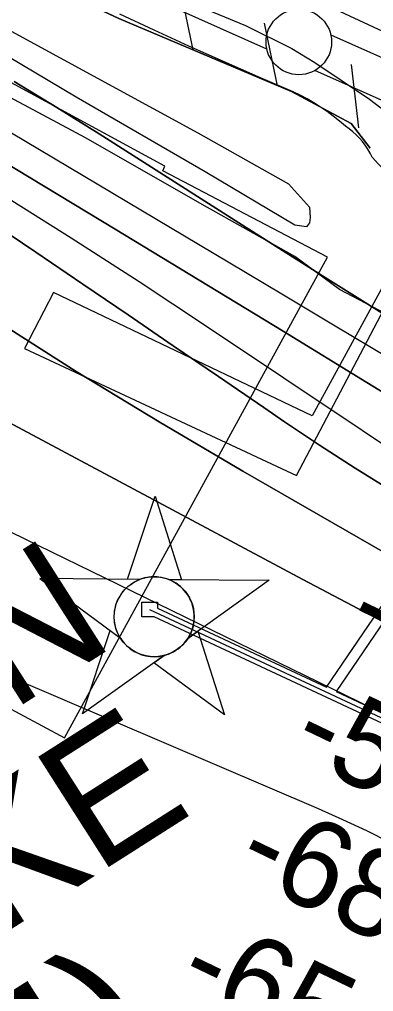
# Model space of a CAD drawing. Extents: x 3704301 to 3742427, y 506229 to 532009.
# Drawn here: x 3708909 to 3709180, y 522807 to 523550 of the extents above; entities that cross this region are included whole.
import ezdxf

# ---------------------------------------------------------------- set-up
doc = ezdxf.new("R2010")
doc.units = 0
for name, color, linetype in [('V-CHAN-DOCK', 7, 'Continuous'), ('V-CHAN-NAID', 7, 'Continuous'), ('V-FLOD-BASE', 7, 'Continuous'), ('V-LEVE-TOET', 7, 'Continuous'), ('V-RIVR-EDGE', 7, 'Continuous'), ('V-RIVR-RANG', 7, 'Continuous'), ('V-RRAP-FSHR', 7, 'Continuous'), ('V-RRAP-RVMT', 7, 'Continuous'), ('V-SITE-VEGE', 7, 'Continuous'), ('V-SURV-LINE', 7, 'Continuous'), ('V-TOPO-DPTH', 7, 'Continuous'), ('V-TOPO-MAJR', 7, 'Continuous'), ('V-TOPO-MINR', 7, 'Continuous'), ('V-TOPO-WATR', 7, 'Continuous'), ('V-UTIL-LINE', 7, 'Continuous')]:
    doc.layers.add(name, color=color, linetype=linetype)

msp = doc.modelspace()

# ---------------------------------------------------------------- linework, layer by layer
at = {"layer": 'V-CHAN-DOCK'}
for points in [[(3709201.26, 523372.33), (3709132.68, 523246.8), (3708935.23, 523340.97), (3708913.04, 523298.3), (3709120.9, 523201.18), (3709208.21, 523367.89), (3709201.26, 523372.33)], [(3709143.74, 523039.46), (3709223.58, 523156.83), (3709280.37, 523238.73), (3709347.55, 523327.59), (3709353.71, 523322.56), (3709286.53, 523233.7), (3709229.73, 523151.8), (3709151, 523036.06), (3709270.29, 522980.22), (3709280.08, 522980.2), (3709280.05, 522969.09), (3709268.05, 522969.11), (3709268.06, 522973.54), (3709012.15, 523093.33), (3709002.64, 523093.35), (3709002.67, 523104.47), (3709014.67, 523104.44), (3709014.66, 523099.89), (3709143.74, 523039.46)]]:
    msp.add_lwpolyline(points, dxfattribs=at)
at = {"layer": 'V-CHAN-NAID'}
for points in [[(3709001.26, 523121.87), (3708991.67, 523121.94), (3709012.8, 523185.42), (3709033.02, 523121.64), (3709023.43, 523121.71), (3709021.86, 523122.29), (3709019.76, 523122.91), (3709017.72, 523123.36), (3709015.69, 523123.67), (3709014.52, 523123.78), (3709012.98, 523123.86), (3709011.26, 523123.86), (3709009.89, 523123.79), (3709007.99, 523123.59), (3709006.62, 523123.37), (3709004.84, 523122.99), (3709003.31, 523122.57), (3709002.27, 523122.24)], [(3709001.26, 523121.87), (3708924.77, 523122.41), (3708986.33, 523077.01), (3708985.22, 523078.92), (3708984.41, 523080.55), (3708983.58, 523082.52), (3708982.89, 523084.57), (3708982.52, 523085.89), (3708982.16, 523087.52), (3708981.92, 523088.96), (3708981.73, 523090.56), (3708981.62, 523092.3), (3708981.61, 523093.88), (3708981.72, 523095.95), (3708981.9, 523097.57), (3708982.29, 523099.77), (3708982.77, 523101.7), (3708983.38, 523103.58), (3708984.03, 523105.26), (3708984.76, 523106.85), (3708985.57, 523108.39), (3708986.63, 523110.12), (3708987.66, 523111.59), (3708988.66, 523112.86), (3708989.67, 523114.01), (3708990.97, 523115.35), (3708992.02, 523116.31), (3708993.74, 523117.71), (3708994.95, 523118.58), (3708996.64, 523119.65), (3708998.37, 523120.59), (3708999.82, 523121.28)], [(3709023.43, 523121.71), (3709099.93, 523121.17), (3709037.72, 523076.65), (3709038.63, 523078.14), (3709039.61, 523079.98), (3709040.33, 523081.57), (3709041.07, 523083.52), (3709041.61, 523085.31), (3709042.01, 523086.95), (3709042.37, 523088.96), (3709042.56, 523090.53), (3709042.68, 523092.73), (3709042.65, 523094.8), (3709042.46, 523097.02), (3709042.2, 523098.78), (3709041.71, 523101.01), (3709041.06, 523103.15), (3709040.31, 523105.13), (3709039.67, 523106.57), (3709038.66, 523108.49), (3709037.6, 523110.21), (3709036.38, 523111.91), (3709035.12, 523113.45), (3709033.85, 523114.82), (3709032.22, 523116.35), (3709030.48, 523117.76), (3709028.79, 523118.94), (3709026.91, 523120.07), (3709025.43, 523120.83)], [(3709019.69, 523063.74), (3708957.49, 523019.22), (3708978.62, 523082.7), (3708986.33, 523077.01), (3708986.97, 523076.05), (3708988.35, 523074.19), (3708989.56, 523072.77), (3708991.03, 523071.27), (3708992.42, 523070.02), (3708993.87, 523068.86), (3708995.27, 523067.88), (3708996.95, 523066.84), (3708998.67, 523065.93), (3709000.46, 523065.12), (3709001.9, 523064.56), (3709003.53, 523064.03), (3709005.76, 523063.47), (3709007.29, 523063.18), (3709009.31, 523062.92), (3709010.85, 523062.82), (3709012.71, 523062.8), (3709014.4, 523062.88), (3709016.11, 523063.05), (3709018.01, 523063.36)], [(3709037.72, 523076.65), (3709045.52, 523082.23), (3709065.74, 523018.45), (3709011.9, 523058.16), (3709019.69, 523063.74), (3709021.36, 523064.22), (3709022.97, 523064.78), (3709025.13, 523065.69), (3709026.86, 523066.57), (3709028.73, 523067.69), (3709030.47, 523068.9), (3709032.02, 523070.15), (3709033.31, 523071.31), (3709034.69, 523072.73), (3709035.9, 523074.14), (3709037.01, 523075.61)]]:
    msp.add_lwpolyline(points, close=True, dxfattribs=at)
msp.add_circle((3709012.14, 523093.33), 30.54, dxfattribs=at)
at = {"layer": 'V-FLOD-BASE'}
msp.add_lwpolyline([(3708672.81, 523755.58), (3708745.33, 523708.9), (3708803.64, 523671.65), (3708829.23, 523656.1), (3708842.97, 523649.03), (3708909.77, 523618.9), (3708991.73, 523582.65), (3709081.74, 523545.01), (3709117.28, 523527.58), (3709134.82, 523516.74), (3709176.53, 523488.92), (3709185.06, 523482.31), (3709195.03, 523472.87), (3709199.78, 523465.31), (3709202.16, 523459.63), (3709201.23, 523449.22), (3709198.42, 523437.86)], dxfattribs=at)
at = {"layer": 'V-LEVE-TOET'}
for points in [[(3709197.72, 523535.35), (3709110.54, 523576.31), (3709007.73, 523622.45), (3708906.81, 523670.48), (3708855.63, 523696.86), (3708767.94, 523754.86), (3708757.73, 523761.46)], [(3709178.5, 523444.5), (3709176.93, 523447.62), (3709175.17, 523450.65), (3709173.22, 523453.56), (3709171.09, 523456.36), (3709168.79, 523459.02), (3709166.33, 523461.54), (3709163.72, 523463.9), (3709160.97, 523466.09), (3709158.09, 523468.12), (3709153.56, 523472.04), (3709148.89, 523475.79), (3709144.08, 523479.37), (3709139.15, 523482.77), (3709134.09, 523485.99), (3709128.93, 523489.03), (3709123.65, 523491.87), (3709118.28, 523494.52), (3709091.61, 523505.96), (3709065.02, 523517.6), (3709038.52, 523529.42), (3709012.11, 523541.45), (3708985.79, 523553.67)], [(3709178.5, 523444.5), (3709183.37, 523439.05), (3709203.89, 523419.31), (3709245.21, 523401.81), (3709256.13, 523405.48), (3709284.61, 523404.06)]]:
    msp.add_lwpolyline(points, dxfattribs=at)
at = {"layer": 'V-RIVR-EDGE'}
msp.add_lwpolyline([(3709189.1, 523324.66), (3709153.73, 523343.35), (3709119.57, 523368.65), (3709048.83, 523408.45), (3708960.11, 523459.1), (3708883.37, 523500.11)], dxfattribs=at)
at = {"layer": 'V-RRAP-FSHR'}
for p, q in [((3709041.95, 523526.47), (3709031.79, 523574.23)), ((3709106.39, 523499.13), (3709096.23, 523546.89)), ((3709168.49, 523466.91), (3709162.78, 523515.4))]:
    msp.add_line(p, q, dxfattribs=at)
for points in [[(3709177.03, 523451.36), (3709162.4, 523470.19), (3709116.88, 523494.68), (3708985.22, 523550.53), (3708890.26, 523595.17), (3708817.73, 523631.58), (3708708.88, 523704.05), (3708608.24, 523768.9), (3708492.61, 523832.14)], [(3708917.78, 523582.24), (3708985.22, 523550.53), (3709116.88, 523494.68), (3709162.4, 523470.19), (3709177.03, 523451.36)], [(3708933.6, 523574.8), (3708985.22, 523550.53), (3709116.88, 523494.68), (3709162.4, 523470.19), (3709177.03, 523451.36)]]:
    msp.add_lwpolyline(points, dxfattribs=at)
at = {"layer": 'V-RRAP-RVMT'}
for p, q in [((3709020.35, 523437.59), (3708894.02, 523506.06)), ((3709018.83, 523434.1), (3709020.35, 523437.59)), ((3709144.49, 523368.14), (3709018.83, 523434.1)), ((3708943.58, 523000.86), (3709144.49, 523368.14)), ((3708432.94, 523273.93), (3708943.58, 523000.86))]:
    msp.add_line(p, q, dxfattribs=at)
at = {"layer": 'V-SITE-VEGE'}
msp.add_lwpolyline([(3708874.63, 523556.08), (3709045.52, 523463.12), (3709114.6, 523424.04), (3709130.69, 523406.24), (3709131.31, 523398.51), (3709130.72, 523394.34), (3709128.35, 523391.36), (3709119.43, 523392.53), (3709050.95, 523433.4), (3708952.69, 523490.25), (3708878.85, 523534.08)], dxfattribs=at)
at = {"layer": 'V-SURV-LINE'}
for points in [[(3709098.2, 523526.99), (3708942.29, 523596.92)], [(3709146.91, 523538.08), (3709674.37, 523303.1)], [(3709662.17, 523275.69), (3709134.71, 523510.67)]]:
    msp.add_lwpolyline(points, dxfattribs=at)
msp.add_circle((3709122.56, 523532.5), 25, dxfattribs=at)
at = {"layer": 'V-TOPO-DPTH'}
for points in [[(3708905.29, 523502.3), (3708937.88, 523482.44), (3708970.25, 523462.21), (3709079.62, 523392.57), (3709110.14, 523373.2), (3709140.69, 523353.87), (3709171.28, 523334.63), (3709201.92, 523315.44)], [(3708812.76, 523491.81), (3708918.01, 523428.33), (3708982.24, 523389.49), (3709046.42, 523350.55), (3709110.51, 523311.48), (3709174.54, 523272.31), (3709245.62, 523228.72), (3709274.39, 523211.89), (3709303.58, 523195.88), (3709333.42, 523181.1), (3709363.68, 523167.13), (3709377.41, 523161.13), (3709407.05, 523148.23), (3709436.72, 523135.38), (3709466.42, 523122.61), (3709496.15, 523109.89), (3709525.58, 523096.6), (3709554.6, 523082.51), (3709583, 523067.22), (3709611, 523051.13), (3710304.55, 522633)], [(3710304.55, 522633), (3709611, 523051.13), (3709583, 523067.22), (3709554.6, 523082.51), (3709525.58, 523096.6), (3709496.15, 523109.89), (3709466.42, 523122.61), (3709436.72, 523135.38), (3709407.05, 523148.23), (3709377.41, 523161.13), (3709363.68, 523167.13), (3709333.42, 523181.1), (3709303.58, 523195.88), (3709274.39, 523211.89), (3709245.62, 523228.72), (3709174.54, 523272.31), (3709110.51, 523311.48), (3709046.42, 523350.55), (3708982.24, 523389.49), (3708918.01, 523428.33), (3708812.76, 523491.81)], [(3709193.07, 523189.83), (3709165.55, 523206.81), (3709138.42, 523224.39), (3709111.54, 523242.37), (3709095.84, 523253.12), (3709061.3, 523276.77), (3709026.73, 523300.39), (3708992.15, 523323.97), (3708957.54, 523347.54), (3708921.81, 523371.84), (3708890.3, 523392.94)], [(3708890.3, 523392.94), (3708921.81, 523371.84), (3708957.54, 523347.54), (3708992.15, 523323.97), (3709026.73, 523300.39), (3709061.3, 523276.77), (3709095.84, 523253.12), (3709111.54, 523242.37), (3709138.42, 523224.39), (3709165.55, 523206.81), (3709193.07, 523189.83)], [(3709708.23, 522809.65), (3709694.45, 522816.02), (3709680.78, 522822.63), (3709667.27, 522829.56), (3709653.88, 522836.72), (3709423.97, 522963.19), (3709393.25, 522980), (3709362.49, 522996.72), (3709331.66, 523013.3), (3709300.78, 523029.8), (3709276.59, 523042.65), (3709257.75, 523052.61), (3709238.87, 523062.53), (3709219.96, 523072.36), (3709201.02, 523082.14), (3709182.08, 523091.93), (3709163.17, 523101.79), (3709144.32, 523111.73), (3709125.49, 523121.74), (3708672.25, 523364.16)], [(3708672.25, 523364.16), (3709125.49, 523121.74), (3709144.32, 523111.73), (3709163.17, 523101.79), (3709182.08, 523091.93), (3709201.02, 523082.14), (3709219.96, 523072.36), (3709238.87, 523062.53), (3709257.75, 523052.61), (3709276.59, 523042.65), (3709300.78, 523029.8), (3709331.66, 523013.3), (3709362.49, 522996.72), (3709393.25, 522980), (3709423.97, 522963.19), (3709653.88, 522836.72), (3709667.27, 522829.56), (3709680.78, 522822.63), (3709694.45, 522816.02), (3709708.23, 522809.65)], [(3709708.54, 522876.08), (3709694.22, 522883.78), (3709679.64, 522890.99), (3709664.89, 522897.87), (3709650, 522904.47), (3709635.09, 522911.05), (3709620.17, 522917.59), (3709605.24, 522924.11), (3709578.34, 522935.81), (3709550.12, 522948.5), (3709522.12, 522961.65), (3709494.46, 522975.49), (3709467.02, 522989.79), (3709318.6, 523069.49), (3709288.39, 523085.89), (3709258.26, 523102.46), (3709228.29, 523119.3), (3709198.41, 523136.32), (3709079.86, 523204.51), (3709015.88, 523242.2), (3708952.45, 523280.76), (3708889.83, 523320.62)], [(3708889.83, 523320.62), (3708952.45, 523280.76), (3709015.88, 523242.2), (3709079.86, 523204.51), (3709198.41, 523136.32), (3709228.29, 523119.3), (3709258.26, 523102.46), (3709288.39, 523085.89), (3709318.6, 523069.49), (3709467.02, 522989.79), (3709494.46, 522975.49), (3709522.12, 522961.65), (3709550.12, 522948.5), (3709578.34, 522935.81), (3709605.24, 522924.11), (3709620.17, 522917.59), (3709635.09, 522911.05), (3709650, 522904.47), (3709664.89, 522897.87), (3709679.64, 522890.99), (3709694.22, 522883.78), (3709708.54, 522876.08)]]:
    msp.add_lwpolyline(points, dxfattribs=at)
at = {"layer": 'V-TOPO-MAJR'}
msp.add_lwpolyline([(3709709.54, 522748.21), (3709681.1, 522763.44), (3709652.55, 522778.47), (3709234.96, 522995.27), (3709223.48, 523001.17), (3709211.97, 523007.02), (3709200.42, 523012.78), (3709188.83, 523018.48), (3708709.33, 523252.26), (3708695.64, 523258.99), (3708681.97, 523265.77), (3708668.35, 523272.64), (3708654.76, 523279.57), (3708641.25, 523286.64), (3708627.81, 523293.85), (3708614.48, 523301.25), (3708601.22, 523308.8), (3708431.37, 523407.12)], dxfattribs=at)
at = {"layer": 'V-TOPO-MINR'}
for points in [[(3710391.59, 522606.43), (3709579.82, 523098.74), (3709549.95, 523115.82), (3709519.57, 523131.86), (3709488.41, 523146.34), (3709456.73, 523159.77), (3709432.16, 523169.45), (3709412.38, 523177.27), (3709392.62, 523185.13), (3709372.88, 523193.04), (3709353.15, 523200.99), (3709351.79, 523201.54), (3709332.97, 523209.67), (3709314.44, 523218.39), (3709296.35, 523227.98), (3709278.55, 523238.16), (3709232.09, 523266.2), (3709191.26, 523290.8), (3709150.4, 523315.34), (3709109.49, 523339.81), (3709068.55, 523364.23), (3708769.51, 523542.19)], [(3710304.55, 522633), (3709611, 523051.13), (3709583, 523067.22), (3709554.6, 523082.51), (3709525.58, 523096.6), (3709496.15, 523109.89), (3709466.42, 523122.61), (3709436.72, 523135.38), (3709407.05, 523148.23), (3709377.41, 523161.13), (3709363.68, 523167.13), (3709333.42, 523181.1), (3709303.58, 523195.88), (3709274.39, 523211.89), (3709245.62, 523228.72), (3709174.54, 523272.31), (3709110.51, 523311.48), (3709046.42, 523350.55), (3708982.24, 523389.49), (3708918.01, 523428.33), (3708812.76, 523491.81)], [(3709230.01, 523196.05), (3709051.97, 523315.21), (3709000.55, 523349.16), (3708948.84, 523382.66), (3708896.7, 523415.5)], [(3709193.07, 523189.83), (3709165.55, 523206.81), (3709138.42, 523224.39), (3709111.54, 523242.37), (3709095.84, 523253.12), (3709061.3, 523276.77), (3709026.73, 523300.39), (3708992.15, 523323.97), (3708957.54, 523347.54), (3708921.81, 523371.84), (3708890.3, 523392.94)], [(3709708.23, 522809.65), (3709694.45, 522816.02), (3709680.78, 522822.63), (3709667.27, 522829.56), (3709653.88, 522836.72), (3709423.97, 522963.19), (3709393.25, 522980), (3709362.49, 522996.72), (3709331.66, 523013.3), (3709300.78, 523029.8), (3709276.59, 523042.65), (3709257.75, 523052.61), (3709238.87, 523062.53), (3709219.96, 523072.36), (3709201.02, 523082.14), (3709182.08, 523091.93), (3709163.17, 523101.79), (3709144.32, 523111.73), (3709125.49, 523121.74), (3708672.25, 523364.16)], [(3709708.54, 522876.08), (3709694.22, 522883.78), (3709679.64, 522890.99), (3709664.89, 522897.87), (3709650, 522904.47), (3709635.09, 522911.05), (3709620.17, 522917.59), (3709605.24, 522924.11), (3709578.34, 522935.81), (3709550.12, 522948.5), (3709522.12, 522961.65), (3709494.46, 522975.49), (3709467.02, 522989.79), (3709318.6, 523069.49), (3709288.39, 523085.89), (3709258.26, 523102.46), (3709228.29, 523119.3), (3709198.41, 523136.32), (3709079.86, 523204.51), (3709015.88, 523242.2), (3708952.45, 523280.76), (3708889.83, 523320.62)], [(3709725.98, 522628.79), (3709707.83, 522639.16), (3709689.6, 522649.37), (3709671.3, 522659.46), (3709210.48, 522911.01), (3709192.55, 522920.47), (3709174.44, 522929.59), (3709156.09, 522938.18), (3709137.56, 522946.43), (3708747.05, 523113.65), (3708718, 523125.84), (3708688.83, 523137.75), (3708659.5, 523149.23), (3708630.05, 523160.44), (3708585.72, 523176.94), (3708578.39, 523179.76), (3708571.11, 523182.7), (3708563.89, 523185.81), (3708556.72, 523189.02), (3708466.78, 523230.6), (3708433.26, 523246.51)]]:
    msp.add_lwpolyline(points, dxfattribs=at)
at = {"layer": 'V-TOPO-WATR'}
msp.add_lwpolyline([(3709201.92, 523315.44), (3709171.28, 523334.63), (3709140.69, 523353.87), (3709110.14, 523373.2), (3709079.62, 523392.57), (3708970.25, 523462.21), (3708937.88, 523482.44), (3708905.29, 523502.3)], dxfattribs=at)
at = {"layer": 'V-UTIL-LINE'}
msp.add_line((3709008.66, 523098.83), (3709274.06, 522974.59), dxfattribs=at)

# ---------------------------------------------------------------- texts
at = {"layer": 'V-CHAN-NAID'}
for s, p in [('CARBON', (3708501.97, 522764.74)), ('COKE', (3708723.9, 522740.27)), ('(89.1) (4)', (3708557.37, 522467.94))]:
    msp.add_text(s, height=100, rotation=32.54019, dxfattribs=at).set_placement(p)
at = {"layer": 'V-RIVR-RANG'}
for s, rotation, p in [('-38', 333.99833, (3709155.5, 523080)), ('-56', 334.28336, (3709113.76, 522988.66)), ('-68', 334.28336, (3709071.57, 522897.98)), ('-65', 334.28336, (3709027.01, 522808.45))]:
    msp.add_text(s, height=67, rotation=rotation, dxfattribs=at).set_placement(p)

doc.saveas('drawing.dxf')
